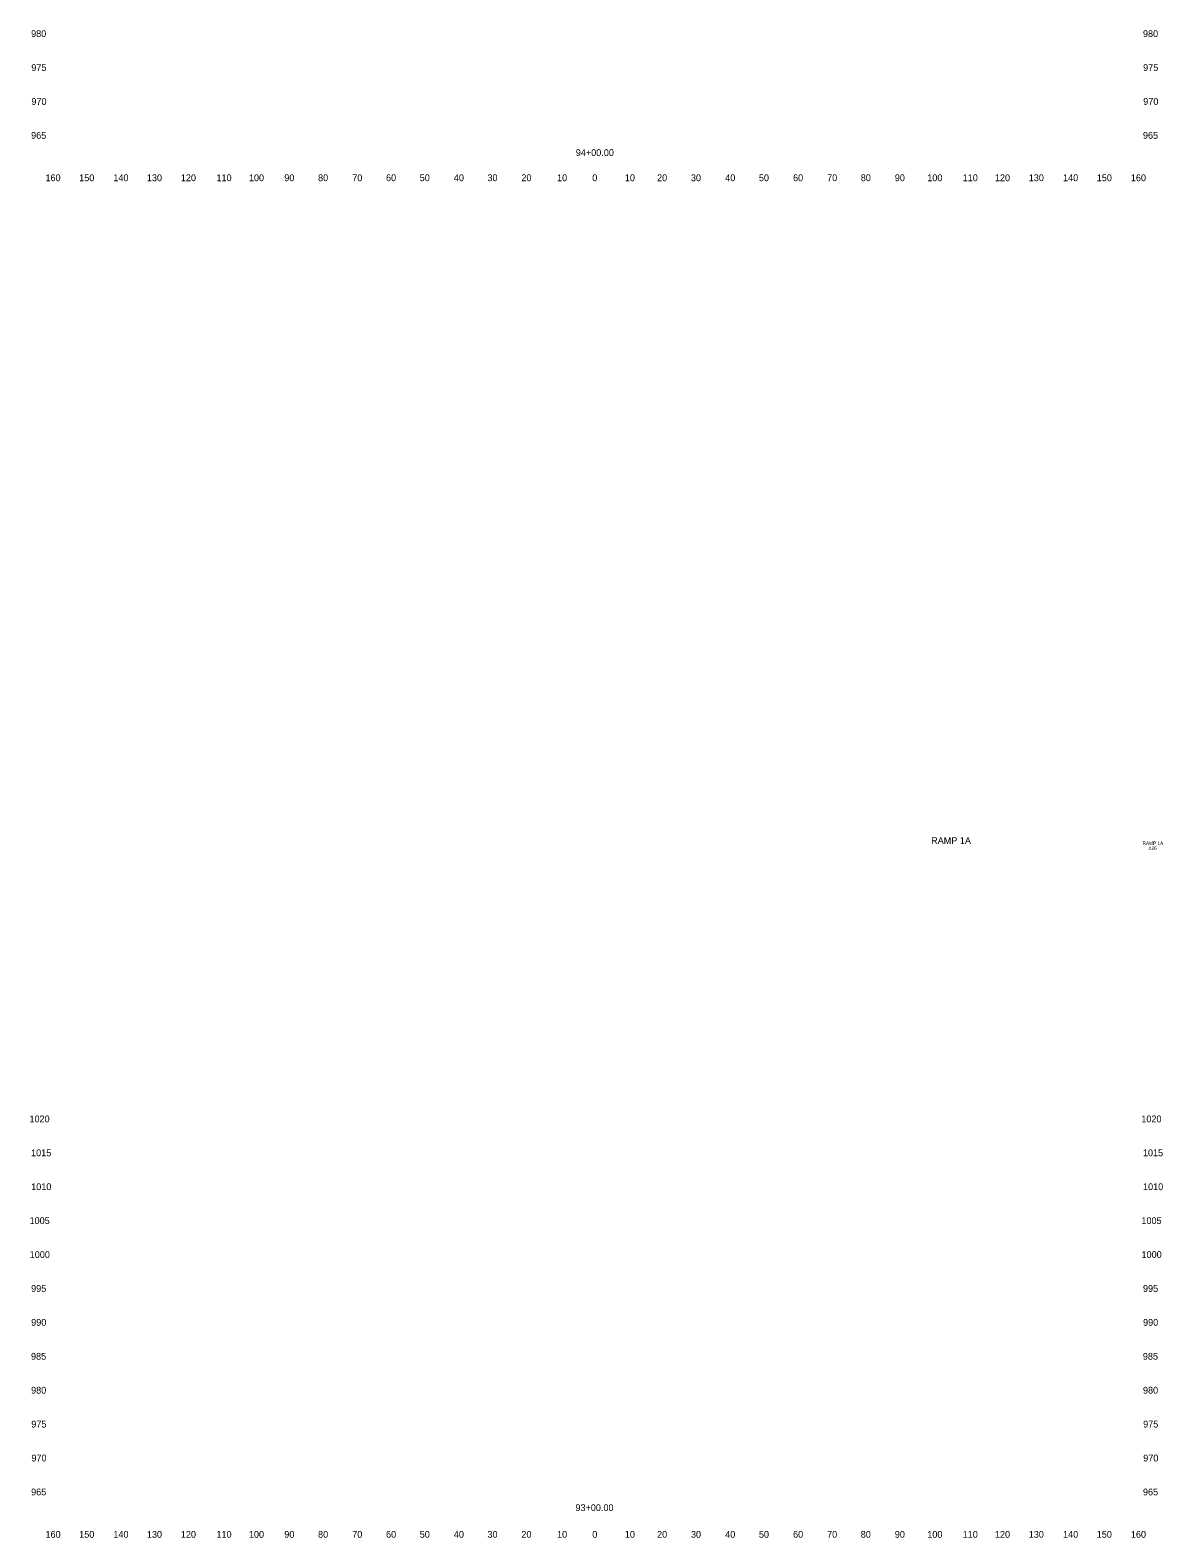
# Model space of a CAD drawing. Extents: x 4994 to 6873, y 4997 to 8804.
# Drawn here: x 6023.6 to 6357.5, y 6997.5 to 7442 of the extents above; entities that cross this region are included whole.
import ezdxf

# ---------------------------------------------------------------- set-up
doc = ezdxf.new("R2010")
doc.units = 0
for name, color, linetype in [('RD_SHT_ID', 7, 'Continuous'), ('RD_XS_TX_Offset', 7, 'Continuous'), ('RD_XS_TX_Station', 7, 'Continuous')]:
    doc.layers.add(name, color=color, linetype=linetype)

msp = doc.modelspace()

# ---------------------------------------------------------------- texts
at = {"layer": 'RD_SHT_ID'}
for s, height, p in [('RAMP 1A', 2, (6289.21, 7202.06)), ('RAMP 1A', 1, (6351.57, 7201.8)), ('X26', 1, (6353.26, 7200.3))]:
    msp.add_text(s, height=height, dxfattribs=at).set_placement(p)
at = {"layer": 'RD_XS_TX_Offset'}
for s, p in [('980', (6023.86, 7440)), ('980', (6351.66, 7440)), ('975', (6023.91, 7430)), ('975', (6351.71, 7430)), ('970', (6023.94, 7420)), ('970', (6351.74, 7420)), ('965', (6023.86, 7410)), ('965', (6351.66, 7410)), ('160', (6028.1, 7397.5)), ('150', (6038.04, 7397.5)), ('140', (6048.1, 7397.5)), ('130', (6057.99, 7397.5)), ('120', (6068.01, 7397.5)), ('110', (6078.51, 7397.5)), ('100', (6088.07, 7397.5)), ('90', (6098.5, 7397.5)), ('80', (6108.46, 7397.5)), ('70', (6118.54, 7397.5)), ('60', (6128.5, 7397.5)), ('50', (6138.43, 7397.5)), ('40', (6148.5, 7397.5)), ('30', (6158.39, 7397.5)), ('20', (6168.4, 7397.5)), ('10', (6178.91, 7397.5)), ('0', (6189.3, 7397.5)), ('0', (6189.3, 7397.5)), ('10', (6198.91, 7397.5)), ('20', (6208.4, 7397.5)), ('30', (6218.39, 7397.5)), ('40', (6228.5, 7397.5)), ('50', (6238.43, 7397.5)), ('60', (6248.5, 7397.5)), ('70', (6258.54, 7397.5)), ('80', (6268.46, 7397.5)), ('90', (6278.5, 7397.5)), ('100', (6288.07, 7397.5)), ('110', (6298.51, 7397.5)), ('120', (6308.01, 7397.5)), ('130', (6317.99, 7397.5)), ('140', (6328.1, 7397.5)), ('150', (6338.04, 7397.5)), ('160', (6348.1, 7397.5)), ('1020', (6023.37, 7120)), ('1020', (6351.17, 7120)), ('1015', (6023.85, 7110)), ('1015', (6351.65, 7110)), ('1010', (6023.88, 7100)), ('1010', (6351.68, 7100)), ('1005', (6023.4, 7090)), ('1005', (6351.2, 7090)), ('1000', (6023.44, 7080)), ('1000', (6351.24, 7080)), ('995', (6023.86, 7070)), ('995', (6351.66, 7070)), ('990', (6023.89, 7060)), ('990', (6351.69, 7060)), ('985', (6023.83, 7050)), ('985', (6351.63, 7050)), ('980', (6023.86, 7040)), ('980', (6351.66, 7040)), ('975', (6023.91, 7030)), ('975', (6351.71, 7030)), ('970', (6023.94, 7020)), ('970', (6351.74, 7020)), ('965', (6023.86, 7010)), ('965', (6351.66, 7010)), ('160', (6028.1, 6997.5)), ('150', (6038.04, 6997.5)), ('140', (6048.1, 6997.5)), ('130', (6057.99, 6997.5)), ('120', (6068.01, 6997.5)), ('110', (6078.51, 6997.5)), ('100', (6088.07, 6997.5)), ('90', (6098.5, 6997.5)), ('80', (6108.46, 6997.5)), ('70', (6118.54, 6997.5)), ('60', (6128.5, 6997.5)), ('50', (6138.43, 6997.5)), ('40', (6148.5, 6997.5)), ('30', (6158.39, 6997.5)), ('20', (6168.4, 6997.5)), ('10', (6178.91, 6997.5)), ('0', (6189.3, 6997.5)), ('0', (6189.3, 6997.5)), ('10', (6198.91, 6997.5)), ('20', (6208.4, 6997.5)), ('30', (6218.39, 6997.5)), ('40', (6228.5, 6997.5)), ('50', (6238.43, 6997.5)), ('60', (6248.5, 6997.5)), ('70', (6258.54, 6997.5)), ('80', (6268.46, 6997.5)), ('90', (6278.5, 6997.5)), ('100', (6288.07, 6997.5)), ('110', (6298.51, 6997.5)), ('120', (6308.01, 6997.5)), ('130', (6317.99, 6997.5)), ('140', (6328.1, 6997.5)), ('150', (6338.04, 6997.5)), ('160', (6348.1, 6997.5))]:
    msp.add_text(s, height=2, dxfattribs=at).set_placement(p)
at = {"layer": 'RD_XS_TX_Station'}
for s, p in [('94+00.00', (6184.45, 7404.92)), ('93+00.00', (6184.34, 7005.37))]:
    msp.add_text(s, height=2, dxfattribs=at).set_placement(p)

doc.saveas('drawing.dxf')
